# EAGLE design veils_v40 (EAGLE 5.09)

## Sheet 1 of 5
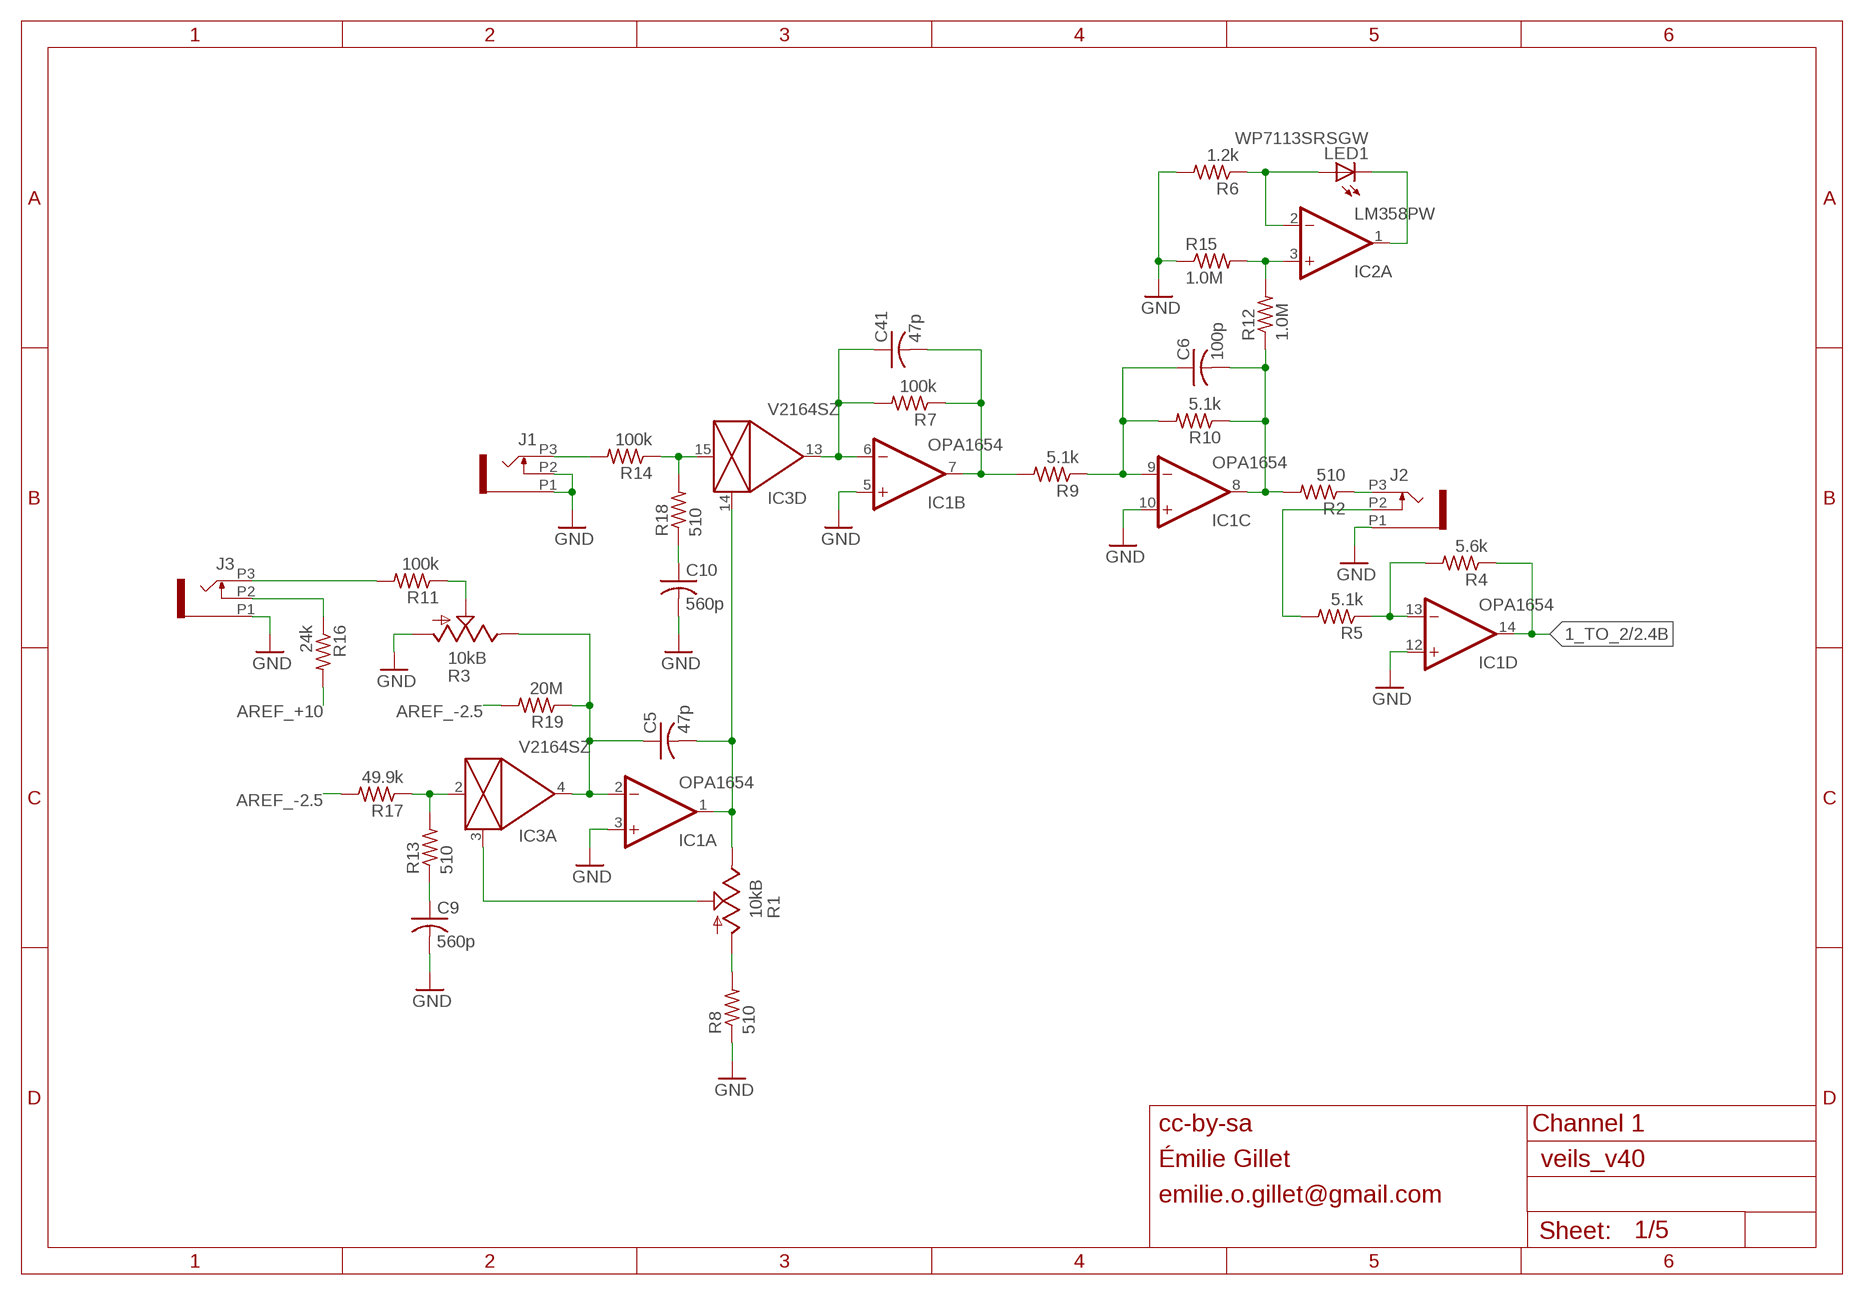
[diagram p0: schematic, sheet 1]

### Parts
C5  47p  C-USC0402  [C0402]
C6  100p  C-USC0402  [C0402]
C9  560p  C-USC0402  [C0402]
C10  560p  C-USC0402  [C0402]
C41  47p  C-USC0402  [C0402]
IC1  OPA1654  TL074PW  [TSSOP14]
IC2  LM358PW  TL072PW  [TSSOP8]
IC3  V2164SZ  SSM2164S  [SOIC16N]
J1  PJ301_THONKICONN6  [WQP_PJ_301M6]
J2  PJ301_THONKICONN6  [WQP_PJ_301M6]
J3  PJ301_THONKICONN6  [WQP_PJ_301M6]
LED1  WP7113SRSGW  LED5MM  [LED5MM]
R1  10kB  POT_USVERTICAL  [ALPS_POT_VERTICAL]
R2  510  R-US_R0402  [R0402]
R3  10kB  POT_USVERTICAL_PS  [ALPS_POT_VERTICAL_PS]
R4  5.6k  R-US_R0402  [R0402]
R5  5.1k  R-US_R0402  [R0402]
R6  1.2k  R-US_R0402  [R0402]
R7  100k  R-US_R0402  [R0402]
R8  510  R-US_R0402  [R0402]
R9  5.1k  R-US_R0402  [R0402]
R10  5.1k  R-US_R0402  [R0402]
R11  100k  R-US_R0402  [R0402]
R12  1.0M  R-US_R0402  [R0402]
R13  510  R-US_R0402  [R0402]
R14  100k  R-US_R0402  [R0402]
R15  1.0M  R-US_R0402  [R0402]
R16  24k  R-US_R0402  [R0402]
R17  49.9k  R-US_R0402  [R0402]
R18  510  R-US_R0402  [R0402]
R19  20M  R-US_R0402  [R0402]

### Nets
1_TO_2: IC1.14(D:OUT) R4.1 ; also sheet 2
AREF_+10: R16.2 ; also sheet 2,3,4,5
AREF_-2.5: R17.2 R19.2 ; also sheet 2,3,4,5
CV_IN_1: J3.P3 R11.2
FOO: IC3.2(A:IN) R13.2 R17.1
GND: C9.2 C10.2 IC1.3(A:+IN) IC1.5(B:+IN) IC1.10(C:+IN) IC1.12(D:+IN) J1.P1 J1.P2 J2.P1 J3.P1 R3.P$3(A) R6.2 R8.1 R15.1 ; also sheet 2,3,4,5
N$1: IC2.3(A:+IN) R12.2 R15.2
N$7: J2.P3 R2.1
N$9: IC3.3(A:CTRL) R1.P$2(S)
N$10: C6.1 IC1.9(C:-IN) R9.1 R10.2
N$14: R3.P$2(S) R11.1
N$15: R1.P$3(A) R8.2
N$18: IC2.1(A:OUT) LED1.K(C)
N$19: IC2.2(A:-IN) LED1.A R6.1
N$20: C9.1 R13.1
N$21: J3.P2 R16.1
N$22: IC1.13(D:-IN) R4.2 R5.1
N$25: J2.P2 R5.2
N$47: C10.1 R18.1
N$65: C5.1 IC1.2(A:-IN) IC3.4(A:OUT) R3.P$1(E) R19.1
N$66: J1.P3 R14.2
N$75: IC3.15(D:IN) R14.1 R18.2
N$87: C5.2 IC1.1(A:OUT) IC3.14(D:CTRL) R1.P$1(E)
N$96: C41.1 IC1.6(B:-IN) IC3.13(D:OUT) R7.2
N$100: C41.2 IC1.7(B:OUT) R7.1 R9.2
OUT1: C6.2 IC1.8(C:OUT) R2.2 R10.1 R12.1

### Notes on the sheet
- cc-by-sa | Channel 1
- Émilie Gillet
- emilie.o.gillet@gmail.com

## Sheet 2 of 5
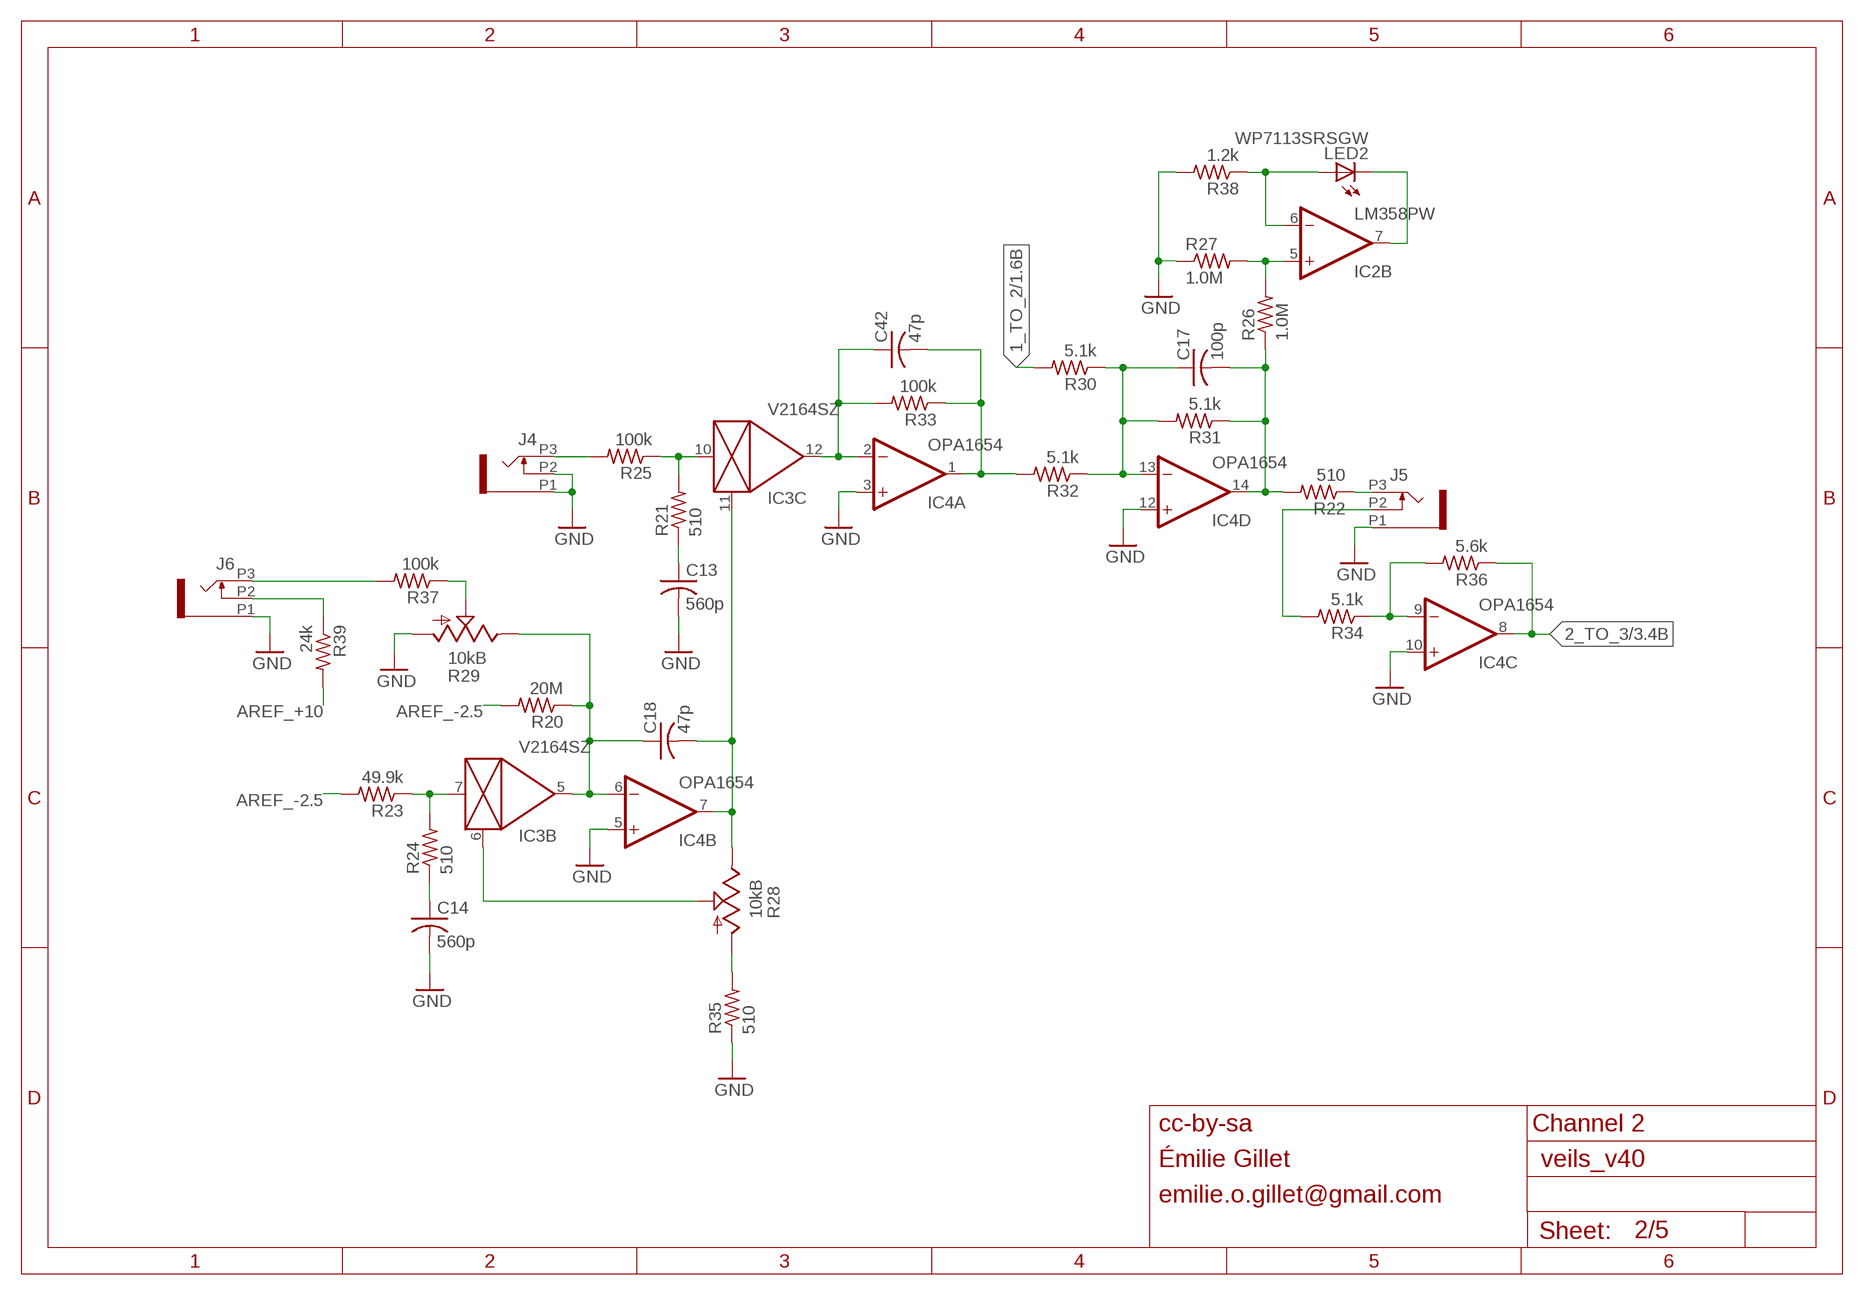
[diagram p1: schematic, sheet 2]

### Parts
C13  560p  C-USC0402  [C0402]
C14  560p  C-USC0402  [C0402]
C17  100p  C-USC0402  [C0402]
C18  47p  C-USC0402  [C0402]
C42  47p  C-USC0402  [C0402]
IC4  OPA1654  TL074PW  [TSSOP14]
J4  PJ301_THONKICONN6  [WQP_PJ_301M6]
J5  PJ301_THONKICONN6  [WQP_PJ_301M6]
J6  PJ301_THONKICONN6  [WQP_PJ_301M6]
LED2  WP7113SRSGW  LED5MM  [LED5MM]
R20  20M  R-US_R0402  [R0402]
R21  510  R-US_R0402  [R0402]
R22  510  R-US_R0402  [R0402]
R23  49.9k  R-US_R0402  [R0402]
R24  510  R-US_R0402  [R0402]
R25  100k  R-US_R0402  [R0402]
R26  1.0M  R-US_R0402  [R0402]
R27  1.0M  R-US_R0402  [R0402]
R28  10kB  POT_USVERTICAL  [ALPS_POT_VERTICAL]
R29  10kB  POT_USVERTICAL_PS  [ALPS_POT_VERTICAL_PS]
R30  5.1k  R-US_R0402  [R0402]
R31  5.1k  R-US_R0402  [R0402]
R32  5.1k  R-US_R0402  [R0402]
R33  100k  R-US_R0402  [R0402]
R34  5.1k  R-US_R0402  [R0402]
R35  510  R-US_R0402  [R0402]
R36  5.6k  R-US_R0402  [R0402]
R37  100k  R-US_R0402  [R0402]
R38  1.2k  R-US_R0402  [R0402]
R39  24k  R-US_R0402  [R0402]

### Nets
1_TO_2: R30.2 ; also sheet 1
2_TO_3: IC4.8(C:OUT) R36.1 ; also sheet 3
AREF_+10: R39.2 ; also sheet 1,3,4,5
AREF_-2.5: R20.2 R23.2 ; also sheet 1,3,4,5
FOO1: IC3.7(B:IN) R23.1 R24.2
GND: C13.2 C14.2 IC4.3(A:+IN) IC4.5(B:+IN) IC4.10(C:+IN) IC4.12(D:+IN) J4.P1 J4.P2 J5.P1 J6.P1 R27.1 R29.P$3(A) R35.1 R38.2 ; also sheet 1,3,4,5
N$3: J4.P3 R25.2
N$4: IC2.5(B:+IN) R26.2 R27.2
N$6: J5.P3 R22.1
N$17: C13.1 R21.1
N$24: IC3.10(C:IN) R21.2 R25.1
N$26: IC3.6(B:CTRL) R28.P$2(S)
N$27: C17.1 IC4.13(D:-IN) R30.1 R31.2 R32.1
N$28: C18.2 IC3.11(C:CTRL) IC4.7(B:OUT) R28.P$1(E)
N$32: R28.P$3(A) R35.2
N$35: IC2.7(B:OUT) LED2.K(C)
N$36: IC2.6(B:-IN) LED2.A R38.1
N$37: IC4.9(C:-IN) R34.1 R36.2
N$38: J5.P2 R34.2
N$39: C42.2 IC4.1(A:OUT) R32.2 R33.1
N$40: R29.P$2(S) R37.1
N$41: C14.1 R24.1
N$42: C18.1 IC3.5(B:OUT) IC4.6(B:-IN) R20.1 R29.P$1(E)
N$44: J6.P3 R37.2
N$53: C42.1 IC3.12(C:OUT) IC4.2(A:-IN) R33.2
N$64: J6.P2 R39.1
OUT2: C17.2 IC4.14(D:OUT) R22.2 R26.1 R31.1

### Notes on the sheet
- cc-by-sa | Channel 2
- Émilie Gillet
- emilie.o.gillet@gmail.com

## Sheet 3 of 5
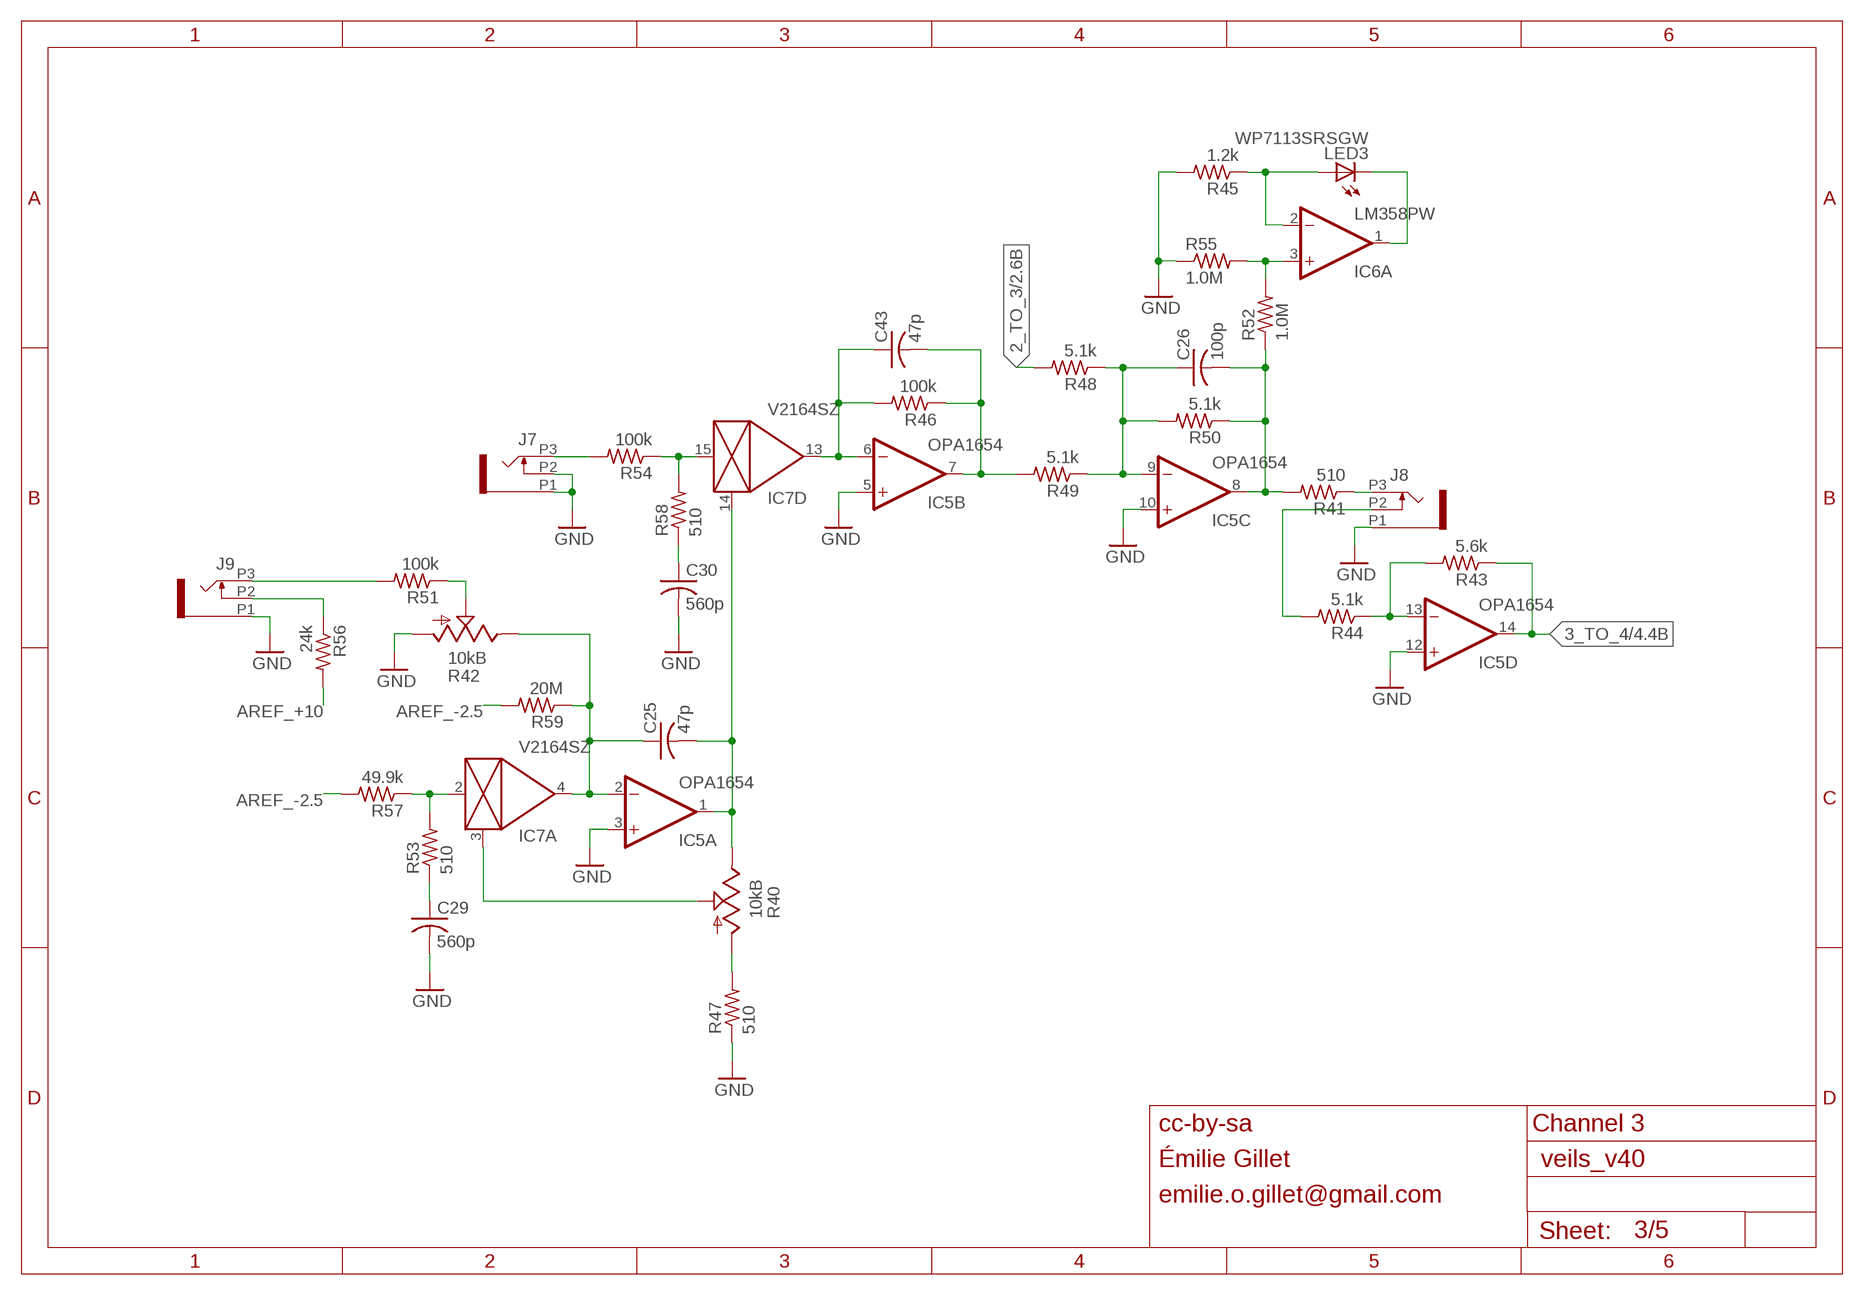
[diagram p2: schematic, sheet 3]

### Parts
C25  47p  C-USC0402  [C0402]
C26  100p  C-USC0402  [C0402]
C29  560p  C-USC0402  [C0402]
C30  560p  C-USC0402  [C0402]
C43  47p  C-USC0402  [C0402]
IC5  OPA1654  TL074PW  [TSSOP14]
IC6  LM358PW  TL072PW  [TSSOP8]
IC7  V2164SZ  SSM2164S  [SOIC16N]
J7  PJ301_THONKICONN6  [WQP_PJ_301M6]
J8  PJ301_THONKICONN6  [WQP_PJ_301M6]
J9  PJ301_THONKICONN6  [WQP_PJ_301M6]
LED3  WP7113SRSGW  LED5MM  [LED5MM]
R40  10kB  POT_USVERTICAL  [ALPS_POT_VERTICAL]
R41  510  R-US_R0402  [R0402]
R42  10kB  POT_USVERTICAL_PS  [ALPS_POT_VERTICAL_PS]
R43  5.6k  R-US_R0402  [R0402]
R44  5.1k  R-US_R0402  [R0402]
R45  1.2k  R-US_R0402  [R0402]
R46  100k  R-US_R0402  [R0402]
R47  510  R-US_R0402  [R0402]
R48  5.1k  R-US_R0402  [R0402]
R49  5.1k  R-US_R0402  [R0402]
R50  5.1k  R-US_R0402  [R0402]
R51  100k  R-US_R0402  [R0402]
R52  1.0M  R-US_R0402  [R0402]
R53  510  R-US_R0402  [R0402]
R54  100k  R-US_R0402  [R0402]
R55  1.0M  R-US_R0402  [R0402]
R56  24k  R-US_R0402  [R0402]
R57  49.9k  R-US_R0402  [R0402]
R58  510  R-US_R0402  [R0402]
R59  20M  R-US_R0402  [R0402]

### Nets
2_TO_3: R48.2 ; also sheet 2
3_TO_4: IC5.14(D:OUT) R43.1 ; also sheet 4
AREF_+10: R56.2 ; also sheet 1,2,4,5
AREF_-2.5: R57.2 R59.2 ; also sheet 1,2,4,5
FOO2: IC7.2(A:IN) R53.2 R57.1
GND: C29.2 C30.2 IC5.3(A:+IN) IC5.5(B:+IN) IC5.10(C:+IN) IC5.12(D:+IN) J7.P1 J7.P2 J8.P1 J9.P1 R42.P$3(A) R45.2 R47.1 R55.1 ; also sheet 1,2,4,5
N$5: IC6.3(A:+IN) R52.2 R55.2
N$23: J8.P3 R41.1
N$29: IC7.3(A:CTRL) R40.P$2(S)
N$30: C25.2 IC5.1(A:OUT) IC7.14(D:CTRL) R40.P$1(E)
N$34: R40.P$3(A) R47.2
N$45: C30.1 R58.1
N$46: IC7.15(D:IN) R54.1 R58.2
N$49: C26.1 IC5.9(C:-IN) R48.1 R49.1 R50.2
N$50: J9.P2 R56.1
N$52: J7.P3 R54.2
N$55: J9.P3 R51.2
N$56: C43.1 IC5.6(B:-IN) IC7.13(D:OUT) R46.2
N$58: IC6.1(A:OUT) LED3.K(C)
N$59: IC6.2(A:-IN) LED3.A R45.1
N$60: IC5.13(D:-IN) R43.2 R44.1
N$61: J8.P2 R44.2
N$63: C29.1 R53.1
N$67: C25.1 IC5.2(A:-IN) IC7.4(A:OUT) R42.P$1(E) R59.1
N$70: R42.P$2(S) R51.1
N$103: C43.2 IC5.7(B:OUT) R46.1 R49.2
OUT3: C26.2 IC5.8(C:OUT) R41.2 R50.1 R52.1

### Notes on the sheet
- cc-by-sa | Channel 3
- Émilie Gillet
- emilie.o.gillet@gmail.com

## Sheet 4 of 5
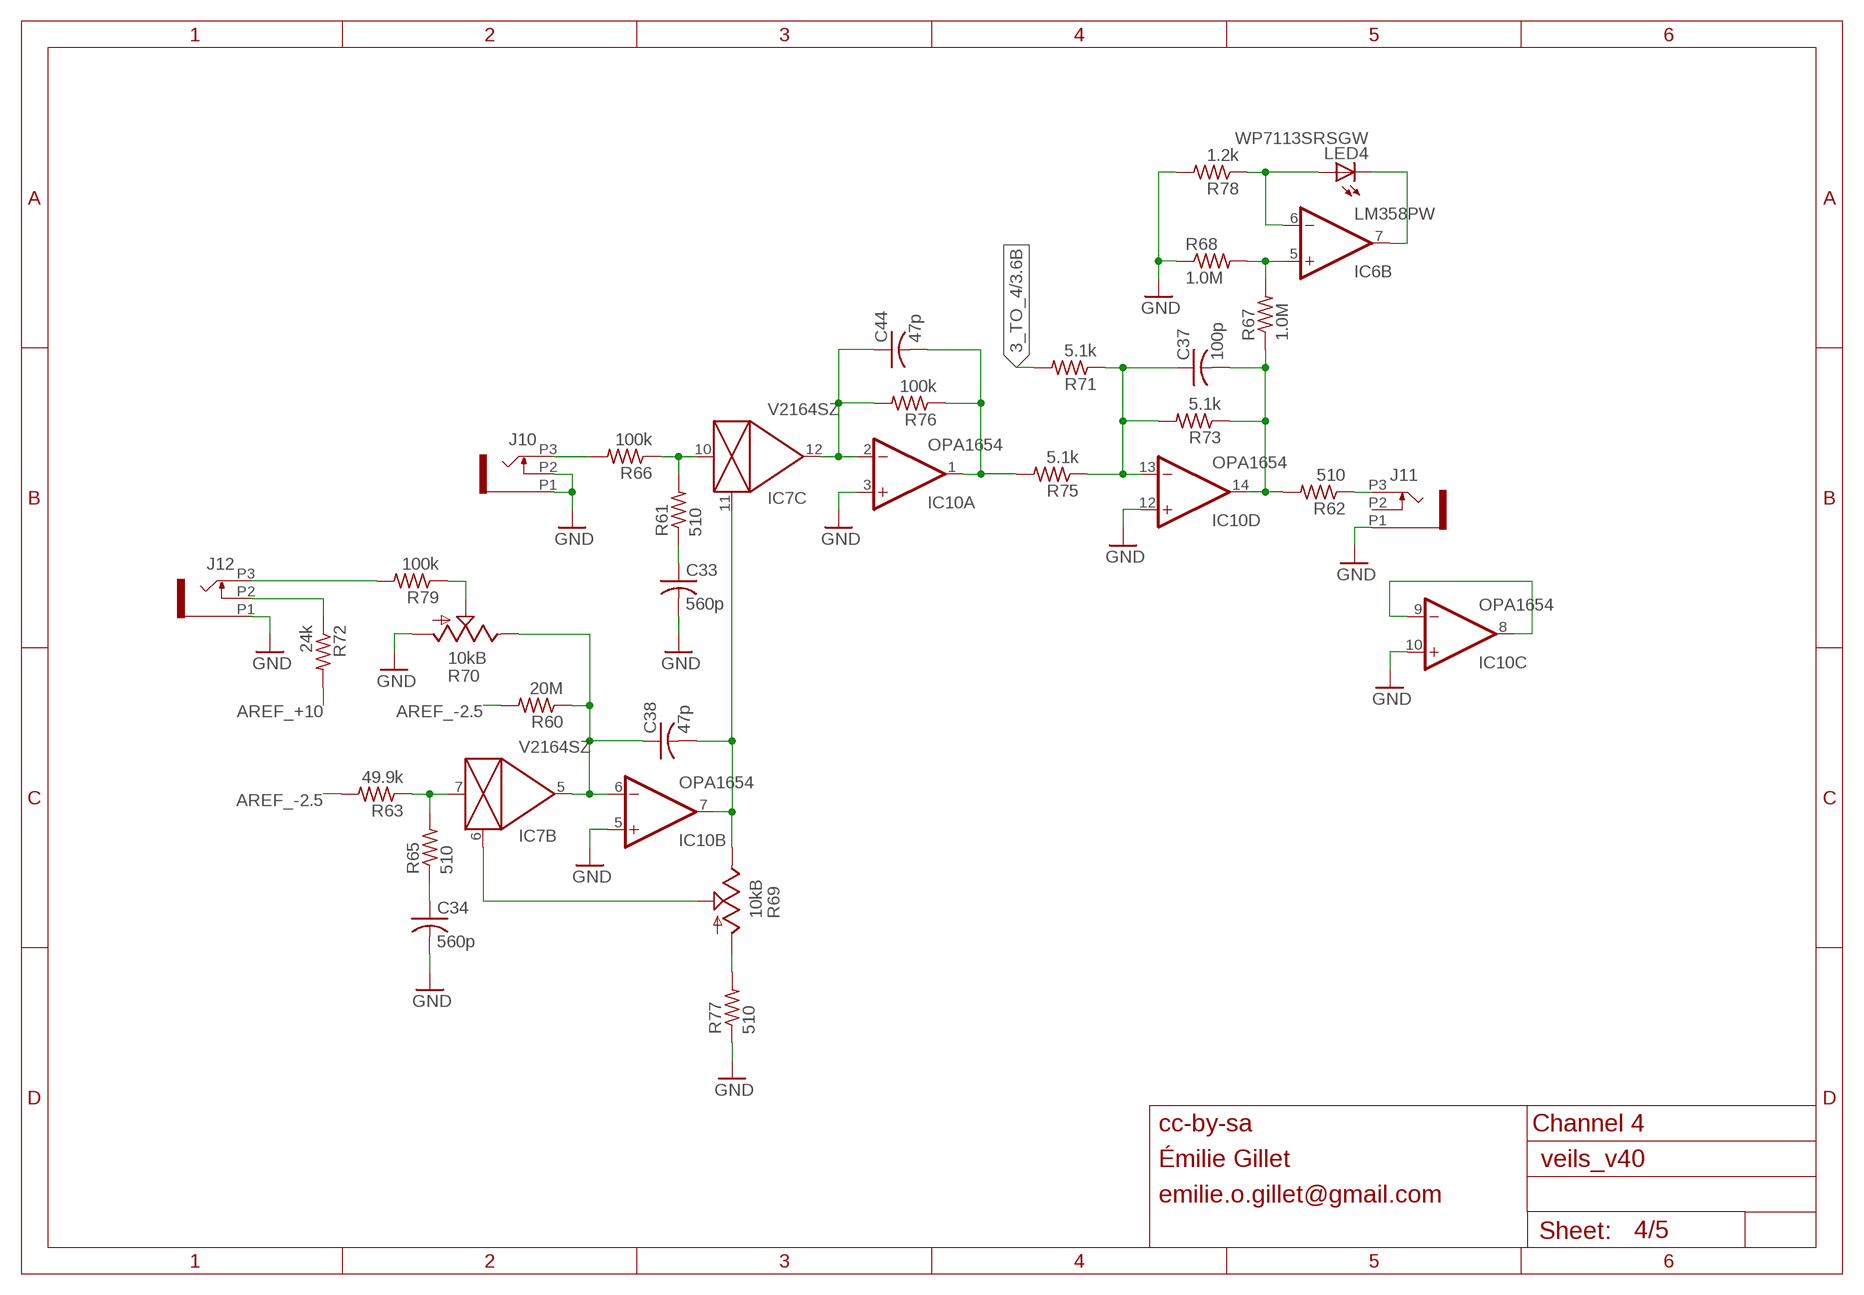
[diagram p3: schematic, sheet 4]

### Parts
C33  560p  C-USC0402  [C0402]
C34  560p  C-USC0402  [C0402]
C37  100p  C-USC0402  [C0402]
C38  47p  C-USC0402  [C0402]
C44  47p  C-USC0402  [C0402]
IC10  OPA1654  TL074PW  [TSSOP14]
J10  PJ301_THONKICONN6  [WQP_PJ_301M6]
J11  PJ301_THONKICONN6  [WQP_PJ_301M6]
J12  PJ301_THONKICONN6  [WQP_PJ_301M6]
LED4  WP7113SRSGW  LED5MM  [LED5MM]
R60  20M  R-US_R0402  [R0402]
R61  510  R-US_R0402  [R0402]
R62  510  R-US_R0402  [R0402]
R63  49.9k  R-US_R0402  [R0402]
R65  510  R-US_R0402  [R0402]
R66  100k  R-US_R0402  [R0402]
R67  1.0M  R-US_R0402  [R0402]
R68  1.0M  R-US_R0402  [R0402]
R69  10kB  POT_USVERTICAL  [ALPS_POT_VERTICAL]
R70  10kB  POT_USVERTICAL_PS  [ALPS_POT_VERTICAL_PS]
R71  5.1k  R-US_R0402  [R0402]
R72  24k  R-US_R0402  [R0402]
R73  5.1k  R-US_R0402  [R0402]
R75  5.1k  R-US_R0402  [R0402]
R76  100k  R-US_R0402  [R0402]
R77  510  R-US_R0402  [R0402]
R78  1.2k  R-US_R0402  [R0402]
R79  100k  R-US_R0402  [R0402]

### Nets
3_TO_4: R71.2 ; also sheet 3
AREF_+10: R72.2 ; also sheet 1,2,3,5
AREF_-2.5: R60.2 R63.2 ; also sheet 1,2,3,5
FOO3: IC7.7(B:IN) R63.1 R65.2
GND: C33.2 C34.2 IC10.3(A:+IN) IC10.5(B:+IN) IC10.10(C:+IN) IC10.12(D:+IN) J10.P1 J10.P2 J11.P1 J12.P1 R68.1 R70.P$3(A) R77.1 R78.2 ; also sheet 1,2,3,5
N$2: IC10.8(C:OUT) IC10.9(C:-IN)
N$8: IC6.5(B:+IN) R67.2 R68.2
N$33: C38.2 IC7.11(C:CTRL) IC10.7(B:OUT) R69.P$1(E)
N$43: IC7.6(B:CTRL) R69.P$2(S)
N$51: R69.P$3(A) R77.2
N$62: C44.1 IC7.12(C:OUT) IC10.2(A:-IN) R76.2
N$69: J10.P3 R66.2
N$71: J11.P3 R62.1
N$72: C33.1 R61.1
N$73: IC7.10(C:IN) R61.2 R66.1
N$76: C37.1 IC10.13(D:-IN) R71.1 R73.2 R75.1
N$77: J12.P3 R79.2
N$84: IC6.7(B:OUT) LED4.K(C)
N$85: IC6.6(B:-IN) LED4.A R78.1
N$88: C44.2 IC10.1(A:OUT) R75.2 R76.1
N$89: R70.P$2(S) R79.1
N$90: C34.1 R65.1
N$91: C38.1 IC7.5(B:OUT) IC10.6(B:-IN) R60.1 R70.P$1(E)
N$105: J12.P2 R72.1
OUT4: C37.2 IC10.14(D:OUT) R62.2 R67.1 R73.1
Unconnected: J11.P2

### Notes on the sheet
- cc-by-sa | Channel 4
- Émilie Gillet
- emilie.o.gillet@gmail.com

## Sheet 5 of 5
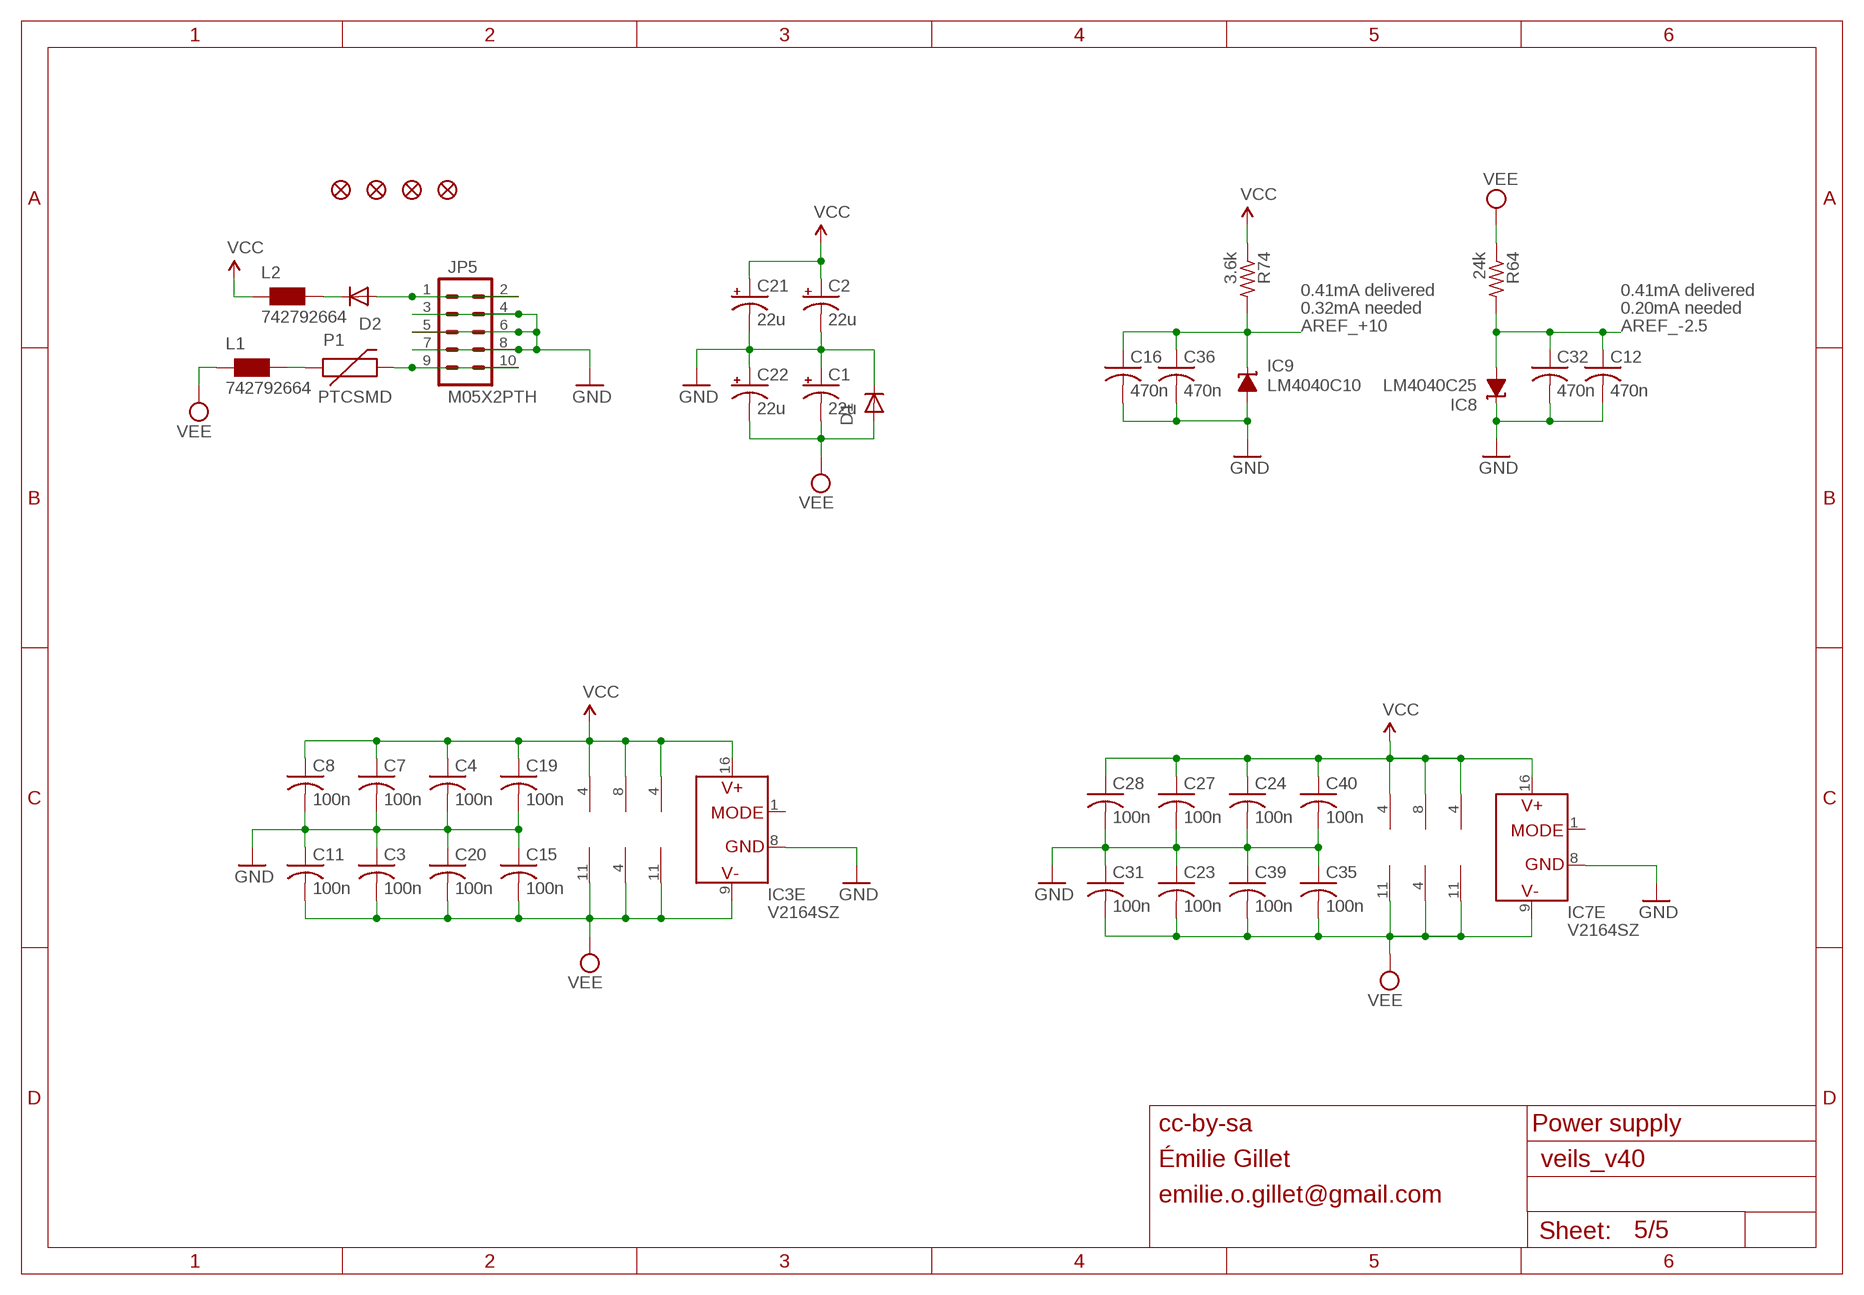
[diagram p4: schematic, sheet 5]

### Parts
C1  22u  CPOL-USB  [PANASONIC_B]
C2  22u  CPOL-USB  [PANASONIC_B]
C3  100n  C-USC0402  [C0402]
C4  100n  C-USC0402  [C0402]
C7  100n  C-USC0402  [C0402]
C8  100n  C-USC0402  [C0402]
C11  100n  C-USC0402  [C0402]
C12  470n  C-USC0402  [C0402]
C15  100n  C-USC0402  [C0402]
C16  470n  C-USC0402  [C0402]
C19  100n  C-USC0402  [C0402]
C20  100n  C-USC0402  [C0402]
C21  22u  CPOL-USB  [PANASONIC_B]
C22  22u  CPOL-USB  [PANASONIC_B]
C23  100n  C-USC0402  [C0402]
C24  100n  C-USC0402  [C0402]
C27  100n  C-USC0402  [C0402]
C28  100n  C-USC0402  [C0402]
C31  100n  C-USC0402  [C0402]
C32  470n  C-USC0402  [C0402]
C35  100n  C-USC0402  [C0402]
C36  470n  C-USC0402  [C0402]
C39  100n  C-USC0402  [C0402]
C40  100n  C-USC0402  [C0402]
D1  1N5819HW  DIODE-SOD123  [SOD123]
D2  1N5819HW  DIODE-SOD123  [SOD123]
IC8  LM4040C25  LM4041B12DBZ  [DBZ_R-PDSO-G3]
IC9  LM4040C10  LM4041B12DBZ  [DBZ_R-PDSO-G3]
JP1  FIDUCIAL1X2  [FIDUCIAL-1X2]
JP2  FIDUCIAL1X2  [FIDUCIAL-1X2]
JP3  FIDUCIAL1X2  [FIDUCIAL-1X2]
JP4  FIDUCIAL1X2  [FIDUCIAL-1X2]
JP5  M05X2PTH  [AVR_ICSP]
L1  742792664  WE-CBF_0603  [0603]
L2  742792664  WE-CBF_0603  [0603]
P1  PTCSMD  [PTC-1206]
R64  24k  R-US_R0402  [R0402]
R74  3.6k  R-US_R0402  [R0402]

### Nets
AREF_+10: C16.1 C36.1 IC9.1(C) R74.2 ; also sheet 1,2,3,4
AREF_-2.5: C12.1 C32.1 IC8.2(A) R64.2 ; also sheet 1,2,3,4
GND: C1.+ C2.- C3.1 C4.2 C7.2 C8.2 C11.1 C12.2 C15.1 C16.2 C19.2 C20.1 C21.- C22.+ C23.1 C24.2 C27.2 C28.2 C31.1 C32.2 C35.1 C36.2 C39.1 C40.2 D1.C IC3.8(E:GND) IC7.8(E:GND) IC8.1(C) IC9.2(A) JP5.3 JP5.4 JP5.5 JP5.6 JP5.7 JP5.8 ; also sheet 1,2,3,4
N$11: D2.A JP5.1 JP5.2
N$12: JP5.9 JP5.10 P1.2
N$13: L1.2 P1.1
N$16: D2.C L2.2
VCC: C2.+ C4.1 C7.1 C8.1 C19.1 C21.+ C24.1 C27.1 C28.1 C40.1 IC1.4(P:V+) IC2.8(P:V+) IC3.16(E:V+) IC4.4(P:V+) IC5.4(P:V+) IC6.8(P:V+) IC7.16(E:V+) IC10.4(P:V+) L2.1 R74.1
VEE: C1.- C3.2 C11.2 C15.2 C20.2 C22.- C23.2 C31.2 C35.2 C39.2 D1.A IC1.11(P:V-) IC2.4(P:V-) IC3.9(E:V-) IC4.11(P:V-) IC5.11(P:V-) IC6.4(P:V-) IC7.9(E:V-) IC10.11(P:V-) L1.1 R64.1
Unconnected: IC3.1(E:MODE) IC7.1(E:MODE)

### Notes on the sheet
- 0.41mA delivered | 0.41mA delivered
- 0.32mA needed | 0.20mA needed
- cc-by-sa | Power supply
- Émilie Gillet
- emilie.o.gillet@gmail.com

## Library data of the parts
C1 C2 C21 C22 = rcl:CPOL-US: POLARIZED CAPACITOR, American symbol
C3-C20 C23-C44 = rcl:C-US: CAPACITOR, American symbol
D1 D2 = diode:DIODE-: DIODE
IC1 IC4 IC5 IC10 = linear:TL074: OP AMP
IC2 IC6 = linear:TL072: OP AMP
IC3 IC7 = ssm2164:SSM2164
IC8 IC9 = texas:LM4041: PRECISION MICROPOWER SHUNT VOLTAGE REFERENCE
J1-J12 = og-pj301:PJ301_THONKICONN
JP1-JP4 = SparkFun:FIDUCIAL: Fiducial Alignment Points
JP5 = og-header:M05X2: Header 5x2 Standard 10-pin dual row 0.1" header. Commonly used with AVR-ISP. Use with Spark Fun Electronics SKU: PRT-00778
L1 L2 = wuerth-elektronik:WE-CBF: SMD EMI Suppression Ferrite Beads
LED1-LED4 = led:LED: LED
P1 = SparkFun:PTC: Resettable Fuse PTC
R1 R28 R40 R69 = og-pots:POT_US
R2 R4-R27 R30-R39 R41 R43-R68 R71-R79 = rcl:R-US_: RESISTOR, American symbol
R3 R29 R42 R70 = pot-alps:POT_US

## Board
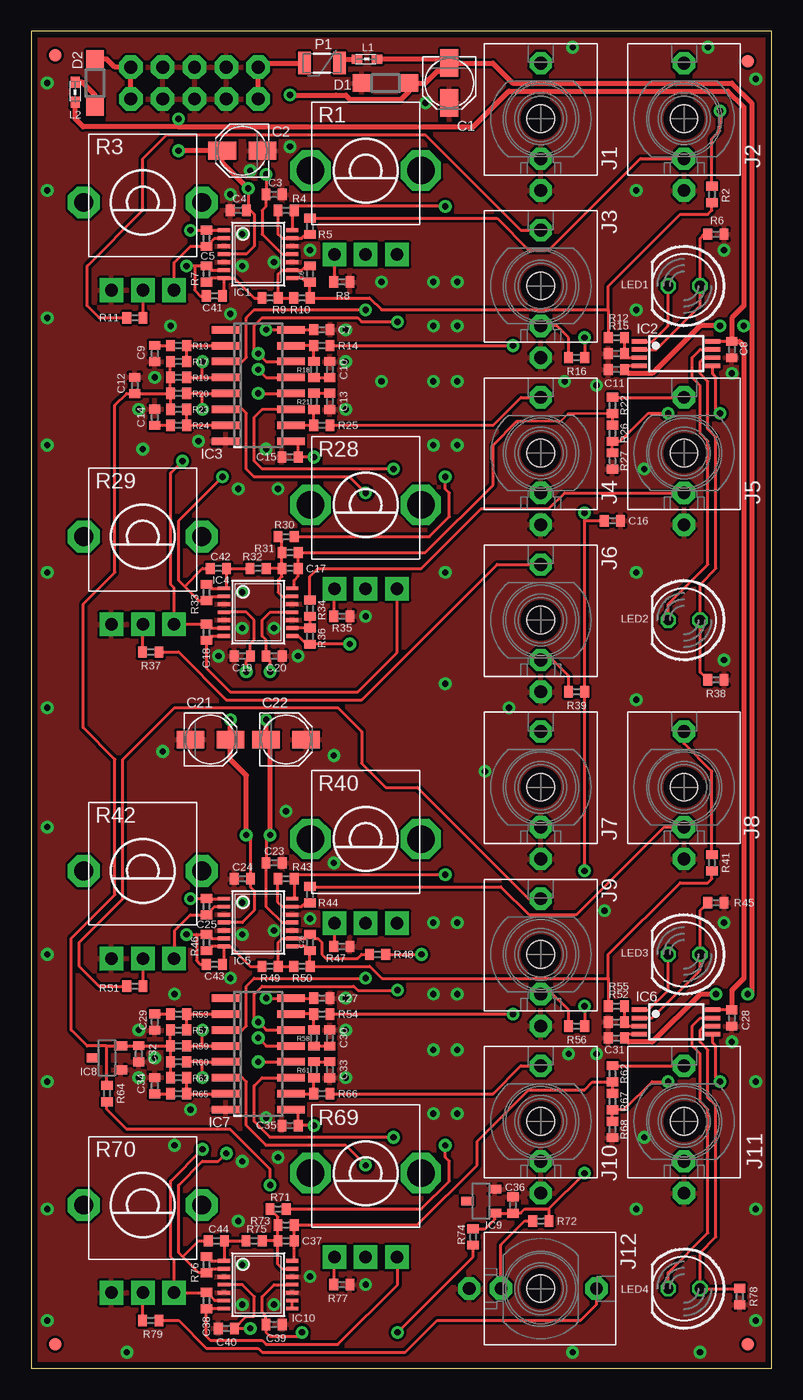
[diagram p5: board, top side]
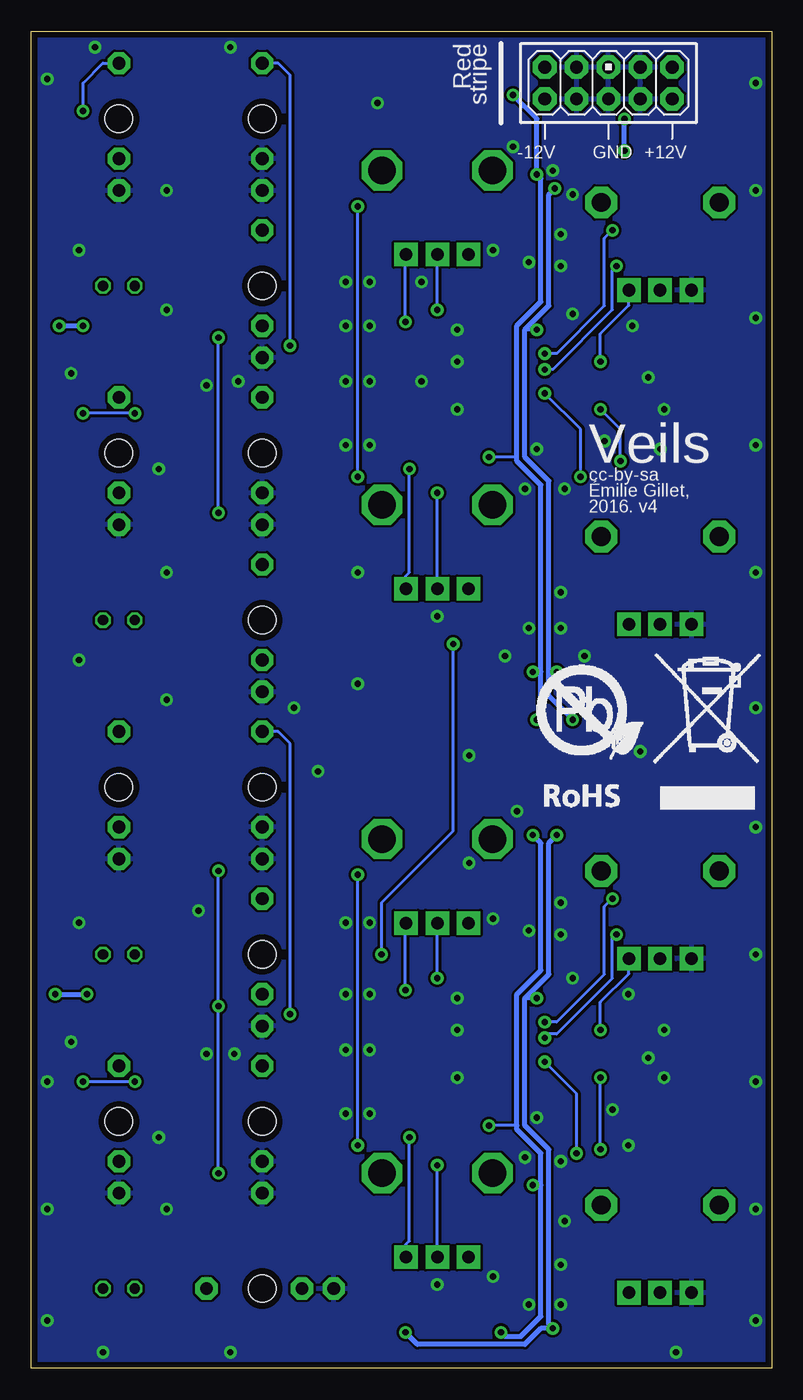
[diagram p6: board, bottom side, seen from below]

Size 59.05 x 106.68 mm. Coordinates in mm from the lower left corner, seen from the top.
Outline: 0,0 59.05,0 59.05,106.68 0,106.68 0,0
Copper layers (1*16): Top 0.035mm / dielectric 1.5mm / Bottom 0.035mm
Design rules "PCBCart-Standard": minimum track width 8mil, minimum drill 0.4mm, track to track 8mil, track to pad 8mil, pad to pad 8mil, via to via 8mil, smd to smd 8mil, copper to edge 20mil, drill to drill 8mil, minimum pad ring 8mil, minimum via ring 10mil, stop-mask expansion 3mil, vias tented up to drill 25mil, thermal gap 8mil

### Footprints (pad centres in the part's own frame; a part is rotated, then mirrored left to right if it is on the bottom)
PANASONIC_B = smd 2.2 x 1.4: + 1.6,0; - -1.6,0
C0402 = smd 0.7 x 0.9: 1 -0.65,0; 2 0.65,0
SOD123 = smd 1.4 x 1.4: A 1.9,0; C -1.9,0
TSSOP14 = smd 0.305 x 0.991: 1 -1.905,-2.718; 2 -1.27,-2.718; 3 -0.635,-2.718; 4 0,-2.718; 5 0.635,-2.718; 6 1.27,-2.718; 7 1.905,-2.718; 8 1.905,2.718; 9 1.27,2.718; 10 0.635,2.718; 11 0,2.718; 12 -0.635,2.718; 13 -1.27,2.718; 14 -1.905,2.718
TSSOP8 = smd 0.35 x 1.2: 1 -0.975,-2.925; 2 -0.325,-2.925; 3 0.325,-2.925; 4 0.975,-2.925; 5 0.975,2.925; 6 0.325,2.925; 7 -0.325,2.925; 8 -0.975,2.925
SOIC16N = smd 0.6 x 2.2: 1 -4.445,-2.6; 2 -3.175,-2.6; 3 -1.905,-2.6; 4 -0.635,-2.6; 5 0.635,-2.6; 6 1.905,-2.6; 7 3.175,-2.6; 8 4.445,-2.6; 9 4.445,2.6; 10 3.175,2.6; 11 1.905,2.6; 12 0.635,2.6; 13 -0.635,2.6; 14 -1.905,2.6; 15 -3.175,2.6; 16 -4.445,2.6
DBZ_R-PDSO-G3 = smd 0.7 x 1: 1 -0.95,-1.1; 2 0.95,-1.1; 3 0,1.1
WQP_PJ_301M6 = drill 1.016 pad 1.778 octagon: P1 0,-5.715; P2 0,-3.175; P3 0,4.445 | hole 2.2: 0,0
FIDUCIAL-1X2 = smd 1 x 1: 1 0,0
AVR_ICSP = drill 1.016 pad 1.88 octagon: 1 -1.27,5.08; 2 1.27,5.08; 3 -1.27,2.54; 4 1.27,2.54; 5 -1.27,0; 6 1.27,0; 7 -1.27,-2.54; 8 1.27,-2.54; 9 -1.27,-5.08; 10 1.27,-5.08
0603 = smd 0.85 x 0.7: 1 -0.9,0; 2 0.7,0
LED5MM = drill 0.813 octagon: A -1.27,0; K 1.27,0
PTC-1206 = smd 1 x 1.8: 1 -1.4,0; 2 1.4,0
ALPS_POT_VERTICAL = drill 1 pad 1.88 square: P$1 -2.5,6.7; P$2 0,6.7; P$3 2.5,6.7 | drill 2.2 pad 3.175 octagon: P$4 -4.4,0; P$5 4.4,0
R0402 = smd 0.7 x 0.9: 1 -0.65,0; 2 0.65,0
ALPS_POT_VERTICAL_PS = drill 1 pad 1.88 square: P$1 -2.5,7; P$2 0,7; P$3 2.5,7 | drill 1.5 pad 2.54 octagon: P$4 -4.7,0; P$5 4.7,0

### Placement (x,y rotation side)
C1  33.34,102.55 270 top
C2  16.83,97.16 180 top
C3  19.37,93.66 180 top
C4  16.51,92.39 180 top
C5  13.97,90.17 90 top
C6  22.23,87.31 270 top
C7  23.18,82.87 0 top
C8  55.88,81.28 270 top
C9  9.84,80.96 270 top
C10  23.81,79.69 90 top
C11  46.67,79.69 0 top
C12  8.26,78.42 90 top
C13  23.81,77.15 270 top
C14  9.84,75.88 90 top
C15  20.64,72.71 0 top
C16  46.35,67.63 0 top
C17  20.64,63.82 0 top
C18  13.97,58.74 270 top
C19  16.83,56.83 180 top
C20  19.37,56.83 180 top
C21  14.29,50.16 0 top
C22  20.32,50.16 0 top
C23  19.37,40.32 180 top
C24  16.83,39.05 180 top
C25  13.97,36.83 90 top
C26  22.23,33.97 270 top
C27  23.18,29.53 0 top
C28  55.88,27.94 270 top
C29  9.84,27.62 270 top
C30  23.81,26.35 90 top
C31  46.67,26.35 0 top
C32  8.57,25.08 270 top
C33  23.81,23.81 270 top
C34  9.84,22.54 90 top
C35  20.64,19.37 0 top
C36  38.42,13.02 90 top
C37  20.32,10.16 0 top
C38  13.97,5.4 270 top
C39  19.37,3.49 180 top
C40  15.56,3.17 180 top
C41  14.61,85.57 0 top
C42  14.92,63.82 0 top
C43  14.61,32.23 0 top
C44  14.76,10.16 0 top
D1  28.26,102.55 0 top
D2  5.08,102.55 90 top
IC1  18.1,88.9 270 top
IC2  51.44,80.96 270 top
IC3  18.1,78.42 270 top
IC4  18.1,60.33 270 top
IC5  18.1,35.56 270 top
IC6  51.44,27.62 270 top
IC7  18.1,25.08 270 top
IC8  6.03,24.77 90 top
IC9  35.88,13.34 90 top
IC10  18.1,6.67 270 top
J1  40.64,99.69 0 top
J2  52.07,99.69 0 top
J3  40.64,86.36 0 top
J4  40.64,73.03 0 top
J5  52.07,73.03 0 top
J6  40.64,59.69 0 top
J7  40.64,46.35 0 top
J8  52.07,46.35 0 top
J9  40.64,33.02 0 top
J10  40.64,19.68 0 top
J11  52.07,19.68 0 top
J12  40.64,6.35 270 top
JP1  1.91,104.78 0 top
JP2  57.15,104.3 0 top
JP3  1.91,1.91 0 top
JP4  57.15,1.91 0 top
JP5  13.02,102.55 270 bottom
L1  26.67,104.46 180 top
L2  3.49,101.92 90 top
LED1  52.07,86.36 180 top
LED2  52.07,59.69 180 top
LED3  52.07,33.02 180 top
LED4  52.07,6.35 180 top
P1  23.18,104.14 180 top
R1  26.67,95.57 180 top
R2  54.29,93.66 270 top
R3  8.89,93.03 180 top
R4  20.32,92.39 180 top
R5  22.23,91.12 90 top
R6  54.61,90.49 0 top
R7  13.97,87.31 90 top
R8  24.77,86.68 180 top
R9  19.05,85.41 180 top
R10  21.59,85.41 180 top
R11  8.26,83.82 180 top
R12  46.67,82.23 0 top
R13  11.75,81.6 0 top
R14  23.18,81.6 0 top
R15  46.67,80.96 0 top
R16  43.5,80.64 0 top
R17  11.75,80.33 180 top
R18  22.54,79.69 90 top
R19  11.75,79.06 180 top
R20  11.75,77.79 180 top
R21  22.54,77.15 270 top
R22  46.35,76.83 270 top
R23  11.75,76.52 180 top
R24  11.75,75.25 0 top
R25  23.18,75.25 0 top
R26  46.35,74.61 270 top
R27  46.35,72.39 90 top
R28  26.67,68.9 180 top
R29  8.89,66.36 180 top
R30  20.32,66.36 0 top
R31  20.64,65.09 180 top
R32  18.1,63.82 180 top
R33  13.97,61.91 270 top
R34  22.23,60.64 90 top
R35  24.77,60.01 180 top
R36  22.23,58.42 90 top
R37  9.53,57.15 0 top
R38  54.61,54.93 0 top
R39  43.5,53.98 0 top
R40  26.67,42.23 180 top
R41  54.29,40.32 270 top
R42  8.89,39.69 180 top
R43  20.32,39.05 180 top
R44  22.23,37.78 90 top
R45  54.61,37.15 0 top
R46  13.97,33.97 90 top
R47  24.77,33.66 180 top
R48  27.62,33.02 0 top
R49  19.05,32.07 180 top
R50  21.59,32.07 180 top
R51  8.26,30.48 180 top
R52  46.67,28.89 0 top
R53  11.75,28.26 0 top
R54  23.18,28.26 0 top
R55  46.67,27.62 0 top
R56  43.5,27.3 0 top
R57  11.75,26.99 180 top
R58  22.54,26.35 90 top
R59  11.75,25.72 180 top
R60  11.75,24.45 180 top
R61  22.54,23.81 270 top
R62  46.35,23.5 270 top
R63  11.75,23.18 180 top
R64  6.03,21.91 90 top
R65  11.75,21.91 0 top
R66  23.18,21.91 0 top
R67  46.35,21.27 270 top
R68  46.35,19.05 90 top
R69  26.67,15.56 180 top
R70  8.89,13.02 180 top
R71  19.68,12.7 0 top
R72  40.64,11.75 0 top
R73  20.32,11.43 180 top
R74  35.24,10.48 90 top
R75  17.78,10.16 180 top
R76  13.97,8.26 270 top
R77  24.77,6.67 180 top
R78  56.52,5.71 270 top
R79  9.53,3.81 0 top
U$2  [ROHS_BIG]  20,43.81 0 bottom

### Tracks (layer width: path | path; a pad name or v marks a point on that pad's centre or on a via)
1_TO_2  (via drill 0.5)
  Top 0.254: v33.02,92.71 21.29,92.71 R4.1 20.82,92.24 IC1.14 | R30.2 31.75,66.36 33.34,67.94 33.34,69.85 33.02,70.17 v33.02,71.12
  Bottom 0.254: v33.02,71.12 v33.02,92.71
2_TO_3  (via drill 0.5)
  Top 0.254: IC4.8 21.27,58.42 21.92,57.77 R36.1 22.24,57.78 v25.4,57.78 | R48.2 v31.11,33.02
  Bottom 0.254: v31.11,33.02 31.11,37.15 25.4,42.86 v25.4,57.78
3_TO_4  (via drill 0.5)
  Top 0.254: R43.1 20.82,38.9 | R43.1 21.29,39.37 v33.02,39.37 | IC5.14 20.97,37.62 R43.1 | R71.2 31.11,12.7 33.34,14.92 33.34,16.51 33.02,16.83 v33.02,17.78
  Bottom 0.254: v33.02,17.78 v33.02,39.37
AREF_+10  (via drill 0.5)
  Top 0.254: R16.2 44.13,80.66 v44.13,82.23 | 41.27,12.7 39.37,12.7 39.05,12.38 38.43,12.38 C36.1 36.99,12.37 IC9.1 36.98,11.89 36.2,11.11 35.26,11.11 R74.2 | 41.27,12.7 v44.13,15.56 | R72.2 41.27,11.76 41.27,12.7 | 44.13,27.32 44.13,27.3 | 44.13,27.32 R56.2 | v44.13,28.89 44.13,27.32 | C16.1 44.13,67.63 v44.13,68.26 44.13,53.99 R39.2 44.15,39.7 v44.13,39.69
  Bottom 0.254: v44.13,68.26 v44.13,82.23 | v44.13,39.69 v44.13,28.89 v44.13,15.56
AREF_-2.5
  Top 0.254: R17.2 R19.2 R20.2 | R20.2 R23.2 | R20.2 8.27,77.79 C12.1 7.61,77.77 6.67,76.83 6.67,63.5 4.13,60.96 4.13,51.12 6.67,48.58 6.67,37.78 3.17,34.29 3.17,26.99 4.45,25.71 6.03,25.71 | R59.2 R57.2 | R63.2 R60.2 R59.2 | R59.2 8.59,25.72 C32.1 7.15,25.73 IC8.2 6.03,25.71 | R64.2 6.03,25.71
CV_IN_1
  Top 0.254: R11.2 5.4,83.82 4.45,84.77 4.45,87.95 8.89,92.39 8.89,96.52 10.79,98.42 31.43,98.42 39.05,90.81 J3.P3
FOO
  Top 0.254: IC3.2 R13.2 R17.1
FOO1
  Top 0.254: R23.1 R24.2 IC3.7
FOO2
  Top 0.254: R57.1 R53.2 IC7.2
FOO3
  Top 0.254: R63.1 R65.2 IC7.7
GND  (via drill 0.5)
  other vias: 55.24,89.22 55.88,79.38 55.88,26.04 55.24,35.56 55.24,56.52 45.09,25.08 48.9,18.41 48.9,71.75 45.09,78.42 43.18,1.27 53.34,1.27 57.78,3.81 57.78,12.7 57.78,22.86 43.18,105.41 53.98,105.41 57.78,102.87 48.26,12.7 48.26,53.34 48.26,63.5 48.26,84.45 48.26,93.98 45.72,36.51 42.55,78.74 42.86,25.08 22.23,35.88 22.23,89.22 16.83,90.49 16.83,87.95 15.88,93.66 20.64,97.47 25.08,82.87 9.84,79.06 8.57,76.52 25.08,80.33 25.08,76.52 13.34,73.98 27.94,86.68 16.83,61.91 16.83,59.05 18.73,73.34 21.27,56.83 26.67,60.01 19.37,88.27 16.51,70.17 19.68,70.17 19.37,59.05 14.92,56.83 10.48,49.21 24.13,48.9 16.83,37.15 16.83,34.61 9.84,24.77 8.57,26.99 8.57,23.18 25.08,26.99 25.08,23.18 25.08,29.53 32.07,35.56 18.73,20 12.7,20.64 16.83,8.26 16.83,5.08 19.37,5.08 16.83,16.51 24.13,40.32 20.32,44.45 11.43,17.78 19.68,16.83 16.51,11.75 22.23,7.3 19.37,34.92 17.46,95.57 1.27,102.55 1.27,93.98 1.27,83.82 1.27,73.66 1.27,63.5 1.27,52.7 1.27,43.18 1.27,33.02 1.27,22.86 1.27,12.7 1.27,3.81 7.62,1.27 32.07,83.19 33.97,83.19 32.07,78.74 33.97,78.74 33.97,73.66 32.07,73.66 32.07,86.68 33.97,86.68 33.02,54.61 36.2,47.62 33.97,35.56 32.07,29.84 33.97,29.84 32.07,25.4 33.97,25.4 32.07,20.32 33.97,20.32 38.1,52.7 33.02,63.5 31.43,100.97 26.67,6.67 15.88,84.14 11.11,83.19 15.88,31.11 11.43,29.84 8.89,73.34 27.94,78.74
  pour Bottom: 0,106.68 0,0 59.05,0 59.05,106.68
  pour Top (isolate 0.203): 0,106.68 0,0 59.05,0 59.05,106.68
N$1
  Top 0.254: R12.2 R15.2 47.65,80.64 IC2.3
N$2
  Top 0.254: IC10.8 IC10.9
N$3
  Top 0.254: J4.P3 39.05,77.47 36.83,75.25 R25.2
N$4  (via drill 0.5)
  Top 0.254: R27.2 R26.2 46.37,73.98 46.99,73.98 49.21,76.2 v50.8,76.2 | v54.93,76.2 54.61,76.52 54.61,79.06 54.36,79.31 IC2.5
  Bottom 0.254: v50.8,76.2 v54.93,76.2
N$5
  Top 0.254: R52.2 R55.2 47.65,27.3 IC6.3
N$6
  Top 0.254: R22.1 46.37,77.47 J5.P3
N$7  (via drill 0.5)
  Top 0.254: R2.1 54.29,98.11 54.93,98.74 v54.93,100.33
  Bottom 0.254: v54.93,100.33 54.93,102.55 53.34,104.14 J2.P3
N$8  (via drill 0.5)
  Top 0.254: R68.2 R67.2 46.37,20.64 47.31,20.64 49.53,22.86 v50.8,22.86 | v54.93,22.86 54.61,23.18 54.61,25.72 54.36,25.97 IC6.5
  Bottom 0.254: v50.8,22.86 v54.93,22.86
N$9  (via drill 0.5)
  Top 0.254: v26.67,84.45 17.78,84.45 17.14,83.82 17.14,80.64 16.83,80.33 IC3.3
  Bottom 0.254: v26.67,84.45 R1.P$2
N$10
  Top 0.254: C6.1 22.21,87.95 21.91,87.95 21.59,87.63 IC1.9 20,87.63 19.68,87.31 19.68,85.42 R9.1 R10.2
N$11
  Top 0.406: D2.A 6.03,104.46 6.67,103.82 JP5.1 JP5.2
N$12
  Top 0.406: JP5.10 JP5.9 18.41,104.14 P1.2
N$13
  Top 0.406: L1.2 24.58,104.46 P1.1
N$14
  Top 0.254: R11.1 8.89,83.83 R3.P$2
N$15
  Top 0.254: R8.2 24.17,86.73 R1.P$3
N$16
  Top 0.406: D2.C | D2.C 5.08,101.6 4.06,102.62 L2.2
N$17
  Top 0.254: R21.1 C13.1
N$18
  Top 0.254: IC2.1 48.53,81.92 49.53,81.92 50.8,83.19 LED1.K
N$19
  Top 0.254: IC2.2 49.85,81.28 53.34,84.77 LED1.A 53.34,90.17 53.66,90.49 R6.1
N$20
  Top 0.254: C9.1 9.86,81.6 R13.1
N$21
  Top 0.254: R16.1 42.86,80.66 42.86,82.23 41.91,83.19 J3.P2
N$22
  Top 0.254: IC1.13 | IC1.13 21.59,90.17 21.89,90.47 R5.1 | R4.2 19.68,92.38 19.68,90.49 20,90.17 IC1.13
N$23
  Top 0.254: J8.P3 52.07,49.85 54.29,47.62 R41.1
N$24
  Top 0.254: R21.2 22.53,76.49 R25.1 IC3.10
N$25
  Top 0.254: J2.P2 48.58,96.52 41.27,89.22 39.69,89.22 37.15,91.76 22.24,91.76 R5.2
N$26  (via drill 0.5)
  Top 0.254: IC3.6 16.83,76.52 17.14,76.2 17.14,71.75 17.78,71.12 25.4,71.12 v26.67,69.85
  Bottom 0.254: R28.P$2 v26.67,69.85
N$27
  Top 0.254: C17.1 R31.2 19.99,66.04 R30.1 | IC4.13 20,61.59 19.68,61.91 19.68,62.87 19.99,63.17 C17.1 | C17.1 R32.1
N$28  (via drill 0.5)
  Top 0.254: IC3.11 18.41,76.52 17.78,75.88 17.78,72.39 18.41,71.75 v28.89,71.75 | IC4.7 14.3,58.42 C18.2 13.97,55.88 15.88,53.98 26.04,53.98 29.17,57.11 R28.P$1
  Bottom 0.254: v28.89,71.75 28.89,63.5 29.17,63.22 R28.P$1
N$29  (via drill 0.5)
  Top 0.254: IC7.3 16.83,26.99 17.14,27.3 17.14,30.48 17.78,31.11 v26.67,31.11
  Bottom 0.254: v26.67,31.11 R40.P$2
N$30  (via drill 0.5)
  Top 0.254: IC5.1 13.98,37.47 C25.2 12.71,37.48 v12.7,37.47 | IC7.14 18.73,26.99 v18.1,27.62 17.78,27.94 17.78,29.84 18.41,30.48 25.72,30.48 26.04,30.16 v29.21,30.16
  Bottom 0.254: v18.1,27.62 17.78,27.62 17.14,27.62 13.34,31.43 13.34,36.83 v12.7,37.47 | R40.P$1 29.21,35.49 v29.21,30.16
N$32
  Top 0.254: R35.2 24.17,60.06 R28.P$3
N$33  (via drill 0.5)
  Top 0.254: IC10.7 13.98,4.76 C38.2 13.97,2.54 14.29,2.22 18.41,2.22 18.73,1.91 24.45,1.91 29.21,6.67 29.21,8.82 R69.P$1 | IC7.11 18.41,23.18 17.78,22.54 17.78,19.68 19.05,18.41 v28.89,18.41
  Bottom 0.254: v28.89,18.41 28.89,10.16 29.17,9.88 R69.P$1
N$34
  Top 0.254: R47.2 24.17,33.71 R40.P$3
N$35
  Top 0.254: LED2.K 50.8,60.96 53.98,64.14 53.98,73.98 53.34,74.61 53.34,78.42 52.7,79.06 52.7,80.64 53.35,81.29 IC2.7
N$36
  Top 0.254: IC2.6 53.66,80.64 53.34,80.33 53.34,79.38 53.98,78.74 53.98,74.93 54.61,74.3 54.61,63.82 53.34,62.55 LED2.A 53.34,55.55 R38.1
N$37
  Top 0.254: IC4.9 20.83,59.07 R36.2 R34.1
N$38
  Top 0.254: J5.P2 42.55,69.85 41.27,68.58 35.88,68.58 31.11,63.82 22.86,63.82 22.23,63.18 R34.2
N$39
  Top 0.254: R33.1 14.3,62.23 IC4.1 15.57,62.42 C42.2 R32.2
N$40
  Top 0.254: R37.1 8.89,57.16 R29.P$2
N$41
  Top 0.254: C14.1 9.86,75.25 R24.1
N$42  (via drill 0.5)
  Top 0.254: 13.65,77.79 IC3.5 | 13.65,77.79 R20.1 | v13.65,76.52 13.65,77.79 | v12.06,72.39 11.11,71.44 11.11,62.55 11.39,62.27 R29.P$1 11.42,59.39 C18.1 14.3,59.05 IC4.6
  Bottom 0.254: v13.65,76.52 12.06,74.93 v12.06,72.39
N$43  (via drill 0.5)
  Top 0.254: IC7.6 16.83,23.18 17.14,22.86 17.14,19.37 18.73,17.78 25.08,17.78 v26.67,16.19
  Bottom 0.254: R69.P$2 v26.67,16.19
N$44
  Top 0.254: J6.P3 37.15,64.14 26.35,53.34 15.56,53.34 11.75,57.15 R37.2
N$45
  Top 0.254: R58.1 C30.1
N$46
  Top 0.254: IC7.15 R54.1 22.53,27.02 R58.2
N$47
  Top 0.254: R18.1 C10.1
N$49
  Top 0.254: R50.2 R49.1 19.7,33.99 20,34.29 IC5.9 21.89,34.29 C26.1 22.56,34.29 22.86,34.29 23.18,33.97 23.18,33.02 23.5,32.7 26.04,32.7 26.35,33.02 R48.1
N$50
  Top 0.254: R56.1 42.86,27.32 42.86,28.57 41.59,29.84 J9.P2
N$51
  Top 0.254: R77.2 24.17,6.72 R69.P$3
N$52  (via drill 0.5)
  Top 0.254: R54.2 v38.42,28.26
  Bottom 0.254: v38.42,28.26 38.42,49.85 39.37,50.8 J7.P3
N$53  (via drill 0.5)
  Top 0.254: IC4.2 14.3,61.59 R33.2 13.35,61.26 12.22,62.39 | v18.1,77.79 IC3.12 | v15.24,71.12 11.75,67.63 11.75,62.87 12.22,62.39 | C42.1 13.65,63.82 12.22,62.39 | 12.22,62.39
  Bottom 0.254: v18.1,77.79 15.24,74.93 v15.24,71.12
N$55
  Top 0.254: R51.2 5.4,30.48 3.81,32.07 3.81,33.97 7.3,37.47 7.3,48.58 11.43,52.7 24.45,52.7 26.35,50.8 26.35,48.26 28.26,46.35 30.8,46.35 39.69,37.47 J9.P3
N$56  (via drill 0.5)
  Top 0.254: IC5.6 14.3,34.29 R46.2 13.18,34.62 | v18.1,26.35 18.73,25.72 IC7.13 | v12.38,34.61 12.4,34.62 13.18,34.62 | C43.1 13.49,32.23 13.18,32.54 13.18,34.62
  Bottom 0.254: v18.1,26.35 17.78,26.67 17.14,26.67 12.7,31.11 12.7,34.29 v12.38,34.61
N$58
  Top 0.254: IC6.1 48.53,28.57 49.21,28.57 50.8,30.16 LED3.K
N$59
  Top 0.254: IC6.2 49.53,27.94 53.34,31.75 LED3.A 53.34,36.53 R45.1
N$60
  Top 0.254: R43.2 19.67,37.16 20,36.83 IC5.13 21.59,36.83 21.89,37.13 R44.1
N$61
  Top 0.254: J8.P2 50.48,43.18 43.5,36.2 39.69,36.2 37.47,38.42 22.24,38.42 R44.2
N$62  (via drill 0.5)
  Top 0.254: 12.06,8.89 13.34,7.62 13.96,7.62 R76.2 14.3,7.94 IC10.2 | 12.06,8.89 11.75,9.21 11.75,14.61 13.65,16.51 14.92,16.51 v15.56,17.14 | v18.1,24.45 IC7.12 | C44.1 13.34,10.16 12.06,8.89
  Bottom 0.254: v15.56,17.14 15.56,21.91 v18.1,24.45
N$63
  Top 0.254: C29.1 9.86,28.26 R53.1
N$64
  Top 0.254: R39.1 42.86,53.99 42.86,55.24 41.59,56.52 J6.P2
N$65  (via drill 0.5)
  Top 0.254: IC1.2 14.62,90.17 C5.1 13.96,89.53 12.7,89.53 11.39,88.22 R3.P$1 | R19.1 13.65,79.06 | 13.65,79.06 IC3.4 | 13.65,79.06 v13.65,80.33
  Bottom 0.254: v13.65,80.33 13.65,82.55 11.39,84.81 R3.P$1
N$66  (via drill 0.5)
  Top 0.254: R14.2 v38.42,81.6
  Bottom 0.254: J1.P3 39.37,104.14 38.42,103.19 v38.42,81.6
N$67  (via drill 0.5)
  Top 0.254: R42.P$1 11.43,32.73 11.43,34.92 12.69,36.18 C25.1 14.62,36.83 IC5.2 | 13.65,25.72 IC7.4 | R59.1 13.65,25.72 | 13.65,25.72 v13.65,26.99
  Bottom 0.254: v13.65,26.99 13.65,29.21 11.39,31.47 R42.P$1
N$69
  Top 0.254: J10.P3 39.05,24.13 36.83,21.91 R66.2
N$70
  Top 0.254: R51.1 8.89,30.5 R42.P$2
N$71
  Top 0.254: R62.1 46.37,24.13 J11.P3
N$72
  Top 0.254: R61.1 C33.1
N$73
  Top 0.254: R61.2 22.54,21.92 R66.1 IC7.10
N$75
  Top 0.254: IC3.15 R14.1 22.53,80.36 R18.2
N$76
  Top 0.254: C37.1 R73.2 19.67,12.06 R71.1 | C37.1 R75.1 | IC10.13 20,7.94 19.67,8.27 C37.1
N$77
  Top 0.254: J12.P3 45.09,5.08 43.81,3.81 32.38,3.81 29.84,1.27 18.41,1.27 18.1,1.59 13.97,1.59 11.75,3.81 R79.2
N$84
  Top 0.254: LED4.K 50.8,7.62 53.98,10.79 53.98,20.64 53.34,21.27 53.34,25.08 52.7,25.72 52.7,27.3 53.35,27.95 IC6.7
N$85
  Top 0.254: IC6.6 53.66,27.3 53.34,26.99 53.34,26.04 53.98,25.4 53.98,21.59 54.61,20.95 54.61,10.48 53.34,9.21 LED4.A 56.5,6.35 R78.1
N$87  (via drill 0.5)
  Top 0.254: IC1.1 13.98,90.81 C5.2 12.71,90.82 v12.7,90.81 | IC3.14 18.73,80.33 v18.1,80.96 17.78,81.28 17.78,83.19 18.41,83.82 26.04,83.82 26.35,83.5 v29.21,83.5
  Bottom 0.254: v18.1,80.96 17.14,80.96 13.34,84.77 13.34,90.17 v12.7,90.81 | R1.P$1 29.21,88.83 v29.21,83.5
N$88
  Top 0.254: R76.1 14.3,8.57 IC10.1 15.41,8.61 C44.2 R75.2
N$89
  Top 0.254: R79.1 8.89,3.83 R70.P$2
N$90
  Top 0.254: C34.1 9.86,21.91 R65.1
N$91  (via drill 0.5)
  Top 0.254: 13.65,24.45 IC7.5 | IC10.6 14.62,5.4 C38.1 13.94,6.02 R70.P$1 11.39,8.61 11.11,8.89 11.11,14.92 v13.65,17.46 | 13.65,24.45 R60.1 | v13.65,23.18 13.65,24.45
  Bottom 0.254: v13.65,17.46 v13.65,23.18
N$96  (via drill 0.5)
  Top 0.254: IC1.6 14.3,87.63 R7.2 13.02,87.96 | v18.1,79.69 18.73,79.06 IC3.13 | v12.38,87.95 12.4,87.96 13.02,87.96 | 13.02,87.96 13.02,86.04 13.49,85.57 C41.1
  Bottom 0.254: v18.1,79.69 17.46,79.69 12.7,84.45 12.7,87.63 v12.38,87.95
N$100
  Top 0.254: R7.1 14.3,87 IC1.7 | IC1.7 | IC1.7 16.19,87 17.78,85.41 R9.2 | C41.2 15.38,85.57 IC1.7
N$103
  Top 0.254: R46.1 14.3,33.66 IC5.7 | IC5.7 15.88,33.66 17.46,32.07 R49.2 | C43.2 15.38,32.35 IC5.7
N$105
  Top 0.254: R72.1 39.37,11.75 37.47,9.84 J12.P2
OUT1
  Top 0.254: R12.1 46.04,82.25 46.04,84.45 | 46.04,84.45 46.04,86.36 51.75,92.08 53.98,92.08 54.29,92.39 R2.2 | 46.04,84.45 27.94,84.45 26.99,85.41 R10.1 22.23,85.42 C6.2 22.21,86.68 21.91,86.68 21.59,87 IC1.8
OUT2
  Top 0.203: 39.05,75.56 42.23,75.56 42.85,76.19 R22.2
  Top 0.254: 46.37,76.2 R22.2 R26.1 | IC4.14 20.95,62.37 20.95,62.87 21.29,63.2 C17.2 R31.1 31.43,65.09 36.83,70.48 36.83,73.66 38.73,75.56 39.05,75.56
OUT3
  Top 0.254: 46.04,31.11 27.94,31.11 26.99,32.07 R50.1 22.23,32.08 C26.2 21.89,33.66 IC5.8 | R52.1 46.04,28.91 46.04,31.11 | 46.04,31.11 46.04,33.02 51.75,38.73 53.98,38.73 54.29,39.05 R41.2
OUT4
  Top 0.254: R62.2 46.37,22.86 | R62.2 R67.1 | R62.2 44.75,22.84 44.13,22.23 39.69,22.23 35.56,18.1 35.56,16.19 30.8,11.43 R73.1 C37.2 20.97,8.73 IC10.14
VCC  (via drill 0.5)
  Top 0.254: C28.1 IC6.8 | C8.1 IC2.8 | IC1.4 17.14,88.9 17.78,89.53 17.78,92.08 17.46,92.39 C4.1 | IC5.4 16.83,35.56 17.78,36.51 17.78,38.1 17.48,38.4 C24.1 17.48,42.21 v17.14,42.55 | 22.54,82.88 C7.1 IC3.16 v18.73,82.87 | C4.1 17.3,92.54 v17.3,94.14 | C4.1 17.14,92.38 | IC4.4 17.14,60.33 17.78,59.69 17.78,58.1 17.48,57.8 C19.1 17.14,56.5 v17.14,55.56 | C27.1 IC7.16 v18.73,29.53 | IC10.4 16.83,6.67 17.8,5.7 17.8,4.14 17.78,4.13 17.14,4.13 16.21,3.19 C40.1 v17.46,3.17 | R74.1 35.24,8.89 v29.21,2.86
  Top 0.406: C28.1 55.88,30.16 56.83,31.11 56.83,81.6 56.5,81.93 C8.1 | C8.1 55.9,81.92 | C8.1 55.88,83.82 56.83,84.77 56.83,100.65 55.56,101.92 38.1,101.92 35.24,99.06 11.75,99.06 | 11.75,99.06 4.13,99.06 3.49,99.69 L2.1 | C2.+ 15.24,97.14 15.24,96.2 v17.3,94.14 | C2.+ | C2.+ v11.75,97.16 | v11.75,99.69 11.75,99.06 | v17.14,42.55 17.14,47.31 15.88,48.58 15.88,50.15 C21.+ 15.88,50.18 v15.88,51.75
  Bottom 0.254: 19.68,82.87 v18.73,82.87 | 17.78,55.56 v17.14,55.56 | 19.68,29.53 v18.73,29.53
  Bottom 0.406: v17.3,94.14 17.78,93.66 17.78,84.77 19.68,82.87 19.68,72.71 17.78,70.8 17.78,55.56 17.78,53.66 v15.88,51.75 | v11.75,97.16 v11.75,99.69 | v17.14,42.55 17.78,41.91 17.78,31.43 19.68,29.53 19.68,19.37 17.78,17.46 17.78,3.49 v17.46,3.17 18.41,3.17 19.68,1.91 28.26,1.91 v29.21,2.86
VEE  (via drill 0.5)
  Top 0.254: IC6.4 48.49,26.67 47.62,26.67 47.32,26.37 C31.2 | IC2.4 48.49,80.01 47.62,80.01 47.32,79.71 C11.2 | IC5.11 20,35.56 18.72,36.84 C23.2 18.73,40.34 18.73,42.23 v19.05,42.55 | v18.73,95.25 18.73,93.68 C3.2 18.72,92.69 18.41,92.39 18.41,90.49 20,88.9 IC1.11 | C15.2 21.27,72.69 | v22.54,72.71 C15.2 | C15.2 21.27,72.72 21.27,73.98 IC3.9 | IC4.11 19.05,60.33 18.41,59.69 18.41,58.42 18.73,58.1 18.73,56.85 C20.2 19.05,56.5 v19.05,55.56 | IC7.9 21.27,20.64 21.29,20.62 C35.2 v22.54,19.37 | IC10.11 19.37,6.67 18.41,5.71 18.41,4.45 18.72,4.14 C39.2 18.72,2.87 19.05,2.54 21.27,2.54 v21.59,2.86 | R64.1 6.03,20.64 7.62,19.05 15.88,19.05 19.05,15.88 v19.05,14.61 | IC1.11
  Top 0.406: 57.47,83.19 57.47,100.97 55.88,102.55 38.42,102.55 36.82,104.15 C1.- | 57.47,83.19 57.47,29.84 v57.15,29.84 | C31.2 47.64,26.04 49.53,26.04 53.34,29.84 v54.61,29.84 | C11.2 47.64,79.38 49.53,79.38 53.34,83.19 v54.93,83.19 | 57.47,83.19 v56.83,83.19 | C1.- 33.34,103.5 32.38,103.5 31.43,102.55 D1.A 30.16,101.91 29.53,101.28 25.4,101.28 25.08,101.6 24.29,101.6 v20.64,101.6 | v19.05,42.55 19.05,49.84 C22.- 18.73,50.18 v18.73,51.75 | L1.1 33.34,104.46 C1.-
  Bottom 0.254: 20.32,72.39 20.32,72.71 v22.54,72.71 | 18.41,55.56 v19.05,55.56 | 20.32,19.37 v22.54,19.37 | 18.41,14.61 v19.05,14.61
  Bottom 0.406: v57.15,29.84 v54.61,29.84 | v56.83,83.19 v54.93,83.19 | v20.64,101.6 18.73,99.69 v18.73,95.25 18.41,94.93 18.41,85.09 20.32,83.19 20.32,72.39 18.41,70.48 18.41,55.56 18.41,52.07 v18.73,51.75 | v19.05,42.55 18.41,41.91 18.41,31.75 20.32,29.84 20.32,19.37 20.32,19.05 18.41,17.14 18.41,14.61 18.41,4.13 20,2.54 21.27,2.54 v21.59,2.86

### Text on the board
bPlace: stripe | Red
bNames: +12V | GND | -12V | Veils | cc-by-sa | Émilie Gillet, | 2016. v4
tStop: Veils | cc-by-sa | Émilie Gillet | 2016. v4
